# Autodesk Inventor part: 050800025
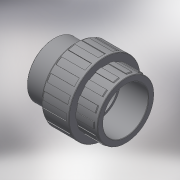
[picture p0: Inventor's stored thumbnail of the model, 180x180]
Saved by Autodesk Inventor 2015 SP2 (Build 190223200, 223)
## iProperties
Created: 2017-10
Part Number: 050800025
Material: Generic
Description: PLASSON UNION+O RING-CEM PVC 25
Document SubType Name: Modeling
Designer: Кирилл
Density: 1 g/cm^3
Appearance: Default
Author: Кирилл
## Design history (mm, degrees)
derived "050800.ipt"
feature "Solid1::050800.ipt"
tag "TaggingFeature1"
body "Solid1"
other parameters: "d0" = 51, "d3" = 25, "d4" = 25, "d6" = 31.25, "d7" = 32, "d8" = 52, "d9" = 19, "d10" = 19, "d11" = 22.5, "d12" = 23.75, "d14" = 14.25, "d15" = 14.25, "d16" = 11.7, "d17" = 1.9, "d19" = 50.96, "d20" = 1.9, "d21" = 1.56, "d25" = 5.2, "d26" = 2.6, "d27" = 18.54, "d28" = 0, "d32" = 5.2, "d33" = 2.6, "d35" = 0, "d39" = 0.25, "d45" = 0.375, "d49" = 360 deg, "d51" = 0.52, "d55" = 360 deg, "d_" = 25, "E_" = 52, "H_" = 51, "l_" = 19, "l_1" = 19, "Z_" = 13, "d13" = 13, "d24" = 20.6, "d40" = 0.375, "d44" = 0.52
